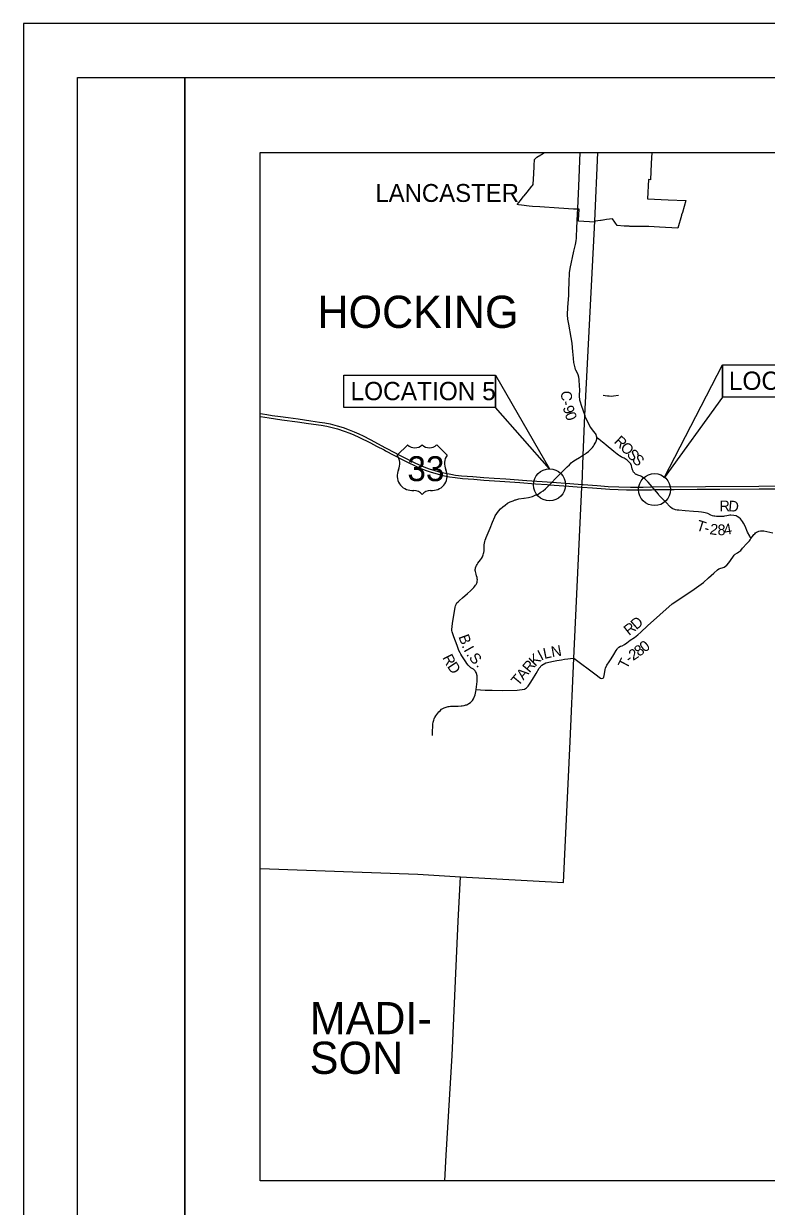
# Model space of a CAD drawing. Extents: x -51.9 to 34, y 0 to 23.3.
# Drawn here: x 0 to 6.91, y 11 to 22 of the extents above; entities that cross this region are included whole.
import ezdxf

# ---------------------------------------------------------------- set-up
doc = ezdxf.new("R2010")
doc.units = 0
for name, color, linetype in [('BR_P_Gen_Text', 7, 'Continuous'), ('Default', 7, 'Continuous'), ('GM_X_Corporation', 7, 'Continuous'), ('GM_X_Corporation_Text', 7, 'Continuous'), ('GM_X_County_Road', 7, 'Continuous'), ('GM_X_County_Road_Text', 7, 'Continuous'), ('GM_X_Minor_River', 7, 'Continuous'), ('GM_X_Township', 7, 'Continuous'), ('GM_X_Township_Road', 7, 'Continuous'), ('GM_X_Township_Road_Text', 7, 'Continuous'), ('GM_X_Township_Text', 7, 'Continuous'), ('GM_X_US_Route', 7, 'Continuous'), ('GM_X_US_Shield', 7, 'Continuous'), ('SH_Border', 7, 'Continuous'), ('SH_Cut_Line', 7, 'Continuous'), ('SH_Text', 7, 'Continuous')]:
    doc.layers.add(name, color=color, linetype=linetype)

msp = doc.modelspace()

# ---------------------------------------------------------------- linework, layer by layer
at = {"layer": 'BR_P_Gen_Text'}
for points in [[(6.501, 18.827), (6.501, 18.527), (5.958, 17.777)], [(6.501, 18.827), (7.909, 18.827), (7.909, 18.527), (6.501, 18.527)], [(2.98, 18.732), (4.389, 18.732), (4.389, 18.431), (2.98, 18.431)], [(4.389, 18.431), (4.389, 18.732), (4.893, 17.86)]]:
    msp.add_lwpolyline(points, close=True, dxfattribs=at)
at = {"layer": 'Default'}
for centre in [(4.893, 17.711), (5.87, 17.666)]:
    msp.add_circle(centre, 0.149, dxfattribs=at)
at = {"layer": 'GM_X_Corporation'}
msp.add_lwpolyline([(5.845, 20.801), (5.839, 20.7), (5.833, 20.548), (5.812, 20.549), (5.805, 20.371), (5.997, 20.362), (6.162, 20.354), (6.129, 20.243), (6.122, 20.221), (6.121, 20.216), (6.087, 20.098), (5.915, 20.108), (5.816, 20.112), (5.805, 20.113), (5.791, 20.113), (5.787, 20.114), (5.699, 20.114), (5.641, 20.114), (5.634, 20.115), (5.588, 20.118), (5.521, 20.124), (5.477, 20.184), (5.422, 20.177), (5.392, 20.173), (5.389, 20.173), (5.372, 20.17), (5.367, 20.17), (5.343, 20.167), (5.313, 20.163), (5.313, 20.157), (5.313, 20.153), (5.162, 20.163), (5.162, 20.173), (5.167, 20.274), (5.159, 20.274), (5.157, 20.274), (5.117, 20.276), (4.979, 20.283), (4.801, 20.297), (4.734, 20.3), (4.702, 20.304), (4.631, 20.312), (4.605, 20.315), (4.591, 20.317), (4.622, 20.354), (4.648, 20.388), (4.652, 20.395), (4.656, 20.4), (4.685, 20.434), (4.729, 20.487), (4.735, 20.496), (4.742, 20.504), (4.747, 20.605), (4.75, 20.672), (4.751, 20.682), (4.754, 20.737), (4.769, 20.752), (4.771, 20.754), (4.776, 20.758), (4.811, 20.78), (4.822, 20.787), (4.847, 20.801), (5.845, 20.801)], dxfattribs=at)
at = {"layer": 'GM_X_County_Road'}
for points in [[(5.156, 20.282), (5.165, 20.487), (5.177, 20.801)], [(5.143, 20.004), (5.145, 20.028), (5.148, 20.089), (5.151, 20.171), (5.156, 20.282)], [(5.334, 18.147), (5.333, 18.154), (5.331, 18.164), (5.326, 18.178), (5.319, 18.188), (5.302, 18.21), (5.276, 18.245), (5.269, 18.255), (5.236, 18.321), (5.228, 18.339), (5.223, 18.353), (5.189, 18.45), (5.18, 18.481), (5.176, 18.499), (5.173, 18.537), (5.174, 18.596), (5.173, 18.628), (5.169, 18.69), (5.166, 18.711), (5.16, 18.733), (5.149, 18.754), (5.138, 18.776), (5.135, 18.783), (5.13, 18.799), (5.12, 18.85), (5.112, 18.923), (5.11, 18.948), (5.102, 19.027), (5.094, 19.081), (5.071, 19.206), (5.063, 19.25), (5.059, 19.292), (5.063, 19.364), (5.071, 19.472), (5.073, 19.519), (5.075, 19.595), (5.079, 19.682), (5.084, 19.723), (5.119, 19.883), (5.133, 19.947), (5.139, 19.979), (5.143, 20.004)], [(5.058, 17.879), (5.078, 17.898), (5.094, 17.914), (5.11, 17.927), (5.133, 17.943), (5.172, 17.965), (5.19, 17.976), (5.206, 17.986), (5.226, 17.999), (5.235, 18.005), (5.256, 18.022), (5.272, 18.037), (5.284, 18.049), (5.291, 18.057), (5.301, 18.07), (5.309, 18.084), (5.317, 18.098), (5.322, 18.107), (5.326, 18.117), (5.33, 18.127), (5.332, 18.134), (5.334, 18.147)], [(4.302, 17.22), (4.339, 17.309), (4.362, 17.364), (4.384, 17.413), (4.388, 17.422), (4.401, 17.445), (4.418, 17.467), (4.437, 17.488), (4.458, 17.506), (4.479, 17.523), (4.503, 17.539), (4.515, 17.546), (4.528, 17.553), (4.553, 17.563), (4.572, 17.57), (4.579, 17.572), (4.606, 17.579), (4.653, 17.587), (4.656, 17.587), (4.697, 17.593), (4.733, 17.603), (4.76, 17.613), (4.786, 17.625), (4.812, 17.641), (4.834, 17.656), (4.856, 17.675), (4.893, 17.711), (4.905, 17.723), (4.916, 17.734), (4.946, 17.765), (4.971, 17.791), (5.027, 17.848), (5.058, 17.879)], [(3.803, 15.379), (3.805, 15.42), (3.807, 15.464), (3.808, 15.485), (3.81, 15.502), (3.813, 15.512), (3.816, 15.523), (3.819, 15.533), (3.824, 15.543), (3.827, 15.548), (3.836, 15.561), (3.864, 15.598), (3.875, 15.61), (3.888, 15.623), (3.894, 15.627), (3.9, 15.631), (3.907, 15.634), (3.913, 15.638), (3.921, 15.641), (3.931, 15.644), (3.94, 15.647), (3.949, 15.649), (3.958, 15.65), (3.971, 15.651), (3.995, 15.652), (4.044, 15.653), (4.071, 15.654), (4.081, 15.655), (4.1, 15.658), (4.107, 15.66), (4.113, 15.663), (4.123, 15.666), (4.133, 15.671), (4.142, 15.676), (4.158, 15.687), (4.167, 15.695), (4.171, 15.7), (4.175, 15.705), (4.185, 15.72), (4.2, 15.758), (4.204, 15.773), (4.208, 15.789), (4.211, 15.808), (4.218, 15.881), (4.22, 15.914), (4.218, 15.935), (4.213, 15.956), (4.209, 15.966), (4.204, 15.976), (4.2, 15.981), (4.196, 15.986), (4.184, 15.996), (4.162, 16.01), (4.152, 16.017), (4.146, 16.023), (4.136, 16.033), (4.124, 16.049), (4.115, 16.063), (4.076, 16.121), (4.068, 16.135), (4.06, 16.149), (4.05, 16.169), (4.032, 16.215), (4.002, 16.297), (3.989, 16.333), (3.986, 16.344), (3.984, 16.355), (3.983, 16.365), (3.989, 16.42), (4.015, 16.572), (4.018, 16.586), (4.02, 16.592), (4.023, 16.597), (4.025, 16.602), (4.031, 16.612), (4.042, 16.624), (4.054, 16.635), (4.083, 16.66), (4.129, 16.699), (4.158, 16.724), (4.173, 16.739), (4.189, 16.755), (4.199, 16.767), (4.205, 16.776), (4.21, 16.785), (4.215, 16.795), (4.218, 16.805), (4.22, 16.816), (4.221, 16.827), (4.22, 16.837), (4.219, 16.848), (4.214, 16.864), (4.209, 16.879), (4.206, 16.891), (4.204, 16.904), (4.202, 16.913), (4.202, 16.923), (4.203, 16.931), (4.204, 16.939), (4.209, 16.953), (4.213, 16.961), (4.218, 16.97), (4.227, 16.983), (4.25, 17.014), (4.26, 17.027), (4.268, 17.041), (4.273, 17.051), (4.276, 17.061), (4.279, 17.071), (4.282, 17.082), (4.284, 17.098), (4.286, 17.152), (4.288, 17.169), (4.291, 17.185), (4.293, 17.196), (4.299, 17.211), (4.302, 17.22)], [(4.211, 15.808), (4.25, 15.805), (4.294, 15.802), (4.359, 15.8), (4.454, 15.799), (4.591, 15.8)]]:
    msp.add_lwpolyline(points, dxfattribs=at)
at = {"layer": 'GM_X_Minor_River'}
msp.add_lwpolyline([(5.535, 18.541), (5.488, 18.535), (5.47, 18.533), (5.449, 18.534), (5.432, 18.536), (5.409, 18.539), (5.392, 18.542)], dxfattribs=at)
at = {"layer": 'GM_X_Township'}
for points in [[(2.202, 14.143), (3.666, 14.088), (4.065, 14.066), (5.024, 14.011), (5.084, 15.323), (5.12, 16.1), (5.194, 17.69), (5.195, 17.715), (5.206, 17.987), (5.222, 18.354), (5.315, 20.164), (5.343, 20.801)], [(3.918, 11.236), (3.931, 11.476), (3.986, 12.402), (4.043, 13.652), (4.065, 14.066)]]:
    msp.add_lwpolyline(points, dxfattribs=at)
at = {"layer": 'GM_X_Township_Road'}
for points in [[(5.788, 17.758), (5.787, 17.759), (5.779, 17.766), (5.77, 17.773), (5.761, 17.779), (5.747, 17.787), (5.737, 17.793), (5.724, 17.798), (5.713, 17.802), (5.703, 17.806), (5.699, 17.808), (5.694, 17.811), (5.69, 17.814), (5.685, 17.817), (5.682, 17.821), (5.678, 17.825), (5.675, 17.83), (5.672, 17.835), (5.67, 17.839), (5.667, 17.844), (5.665, 17.851), (5.662, 17.861), (5.659, 17.876), (5.656, 17.886), (5.654, 17.893), (5.65, 17.9), (5.648, 17.905), (5.642, 17.913), (5.634, 17.921), (5.626, 17.929), (5.614, 17.939), (5.605, 17.946), (5.596, 17.952), (5.586, 17.958), (5.577, 17.963), (5.57, 17.966), (5.559, 17.972), (5.545, 17.98), (5.533, 17.988), (5.521, 17.996), (5.491, 18.021), (5.42, 18.08), (5.398, 18.098), (5.384, 18.109), (5.371, 18.12), (5.348, 18.137), (5.334, 18.147)], [(5.91, 17.616), (5.905, 17.623), (5.87, 17.666), (5.858, 17.68), (5.848, 17.691), (5.809, 17.735), (5.788, 17.758)], [(6.766, 17.211), (6.755, 17.232), (6.736, 17.271), (6.712, 17.325), (6.697, 17.354), (6.689, 17.369), (6.669, 17.395), (6.655, 17.408), (6.639, 17.417), (6.629, 17.421), (6.608, 17.426), (6.581, 17.428), (6.57, 17.427), (6.559, 17.426), (6.543, 17.423), (6.522, 17.418), (6.511, 17.416), (6.49, 17.415), (6.469, 17.415), (6.447, 17.416), (6.431, 17.418), (6.42, 17.42), (6.41, 17.423), (6.394, 17.429), (6.364, 17.443), (6.342, 17.449), (6.326, 17.453), (6.306, 17.456), (6.279, 17.46), (6.231, 17.464), (6.156, 17.47), (6.096, 17.474), (6.079, 17.476), (6.065, 17.478), (6.057, 17.48), (6.04, 17.487), (6.033, 17.492), (6.019, 17.503), (5.972, 17.551), (5.924, 17.598), (5.911, 17.615), (5.91, 17.616)], [(6.766, 17.211), (6.78, 17.23), (6.795, 17.248), (6.802, 17.256), (6.81, 17.263), (6.819, 17.27), (6.828, 17.275), (6.839, 17.279), (6.855, 17.283), (6.866, 17.284), (6.877, 17.284), (6.887, 17.282), (6.969, 17.265)], [(5.113, 16.099), (5.12, 16.099), (5.327, 15.945), (5.356, 15.922), (5.368, 15.914), (5.378, 15.909), (5.388, 15.912), (5.396, 15.917), (5.398, 15.923), (5.402, 15.938), (5.408, 15.972), (5.411, 15.994), (5.413, 16.007), (5.426, 16.034), (5.446, 16.063), (5.467, 16.093), (5.49, 16.134), (5.512, 16.171), (5.523, 16.183), (5.526, 16.187), (5.537, 16.2), (5.554, 16.209), (5.569, 16.214), (5.589, 16.227), (5.613, 16.241), (5.643, 16.265), (5.683, 16.292), (5.713, 16.316), (5.743, 16.34), (5.805, 16.398), (6.034, 16.603), (6.216, 16.725), (6.324, 16.802), (6.371, 16.847), (6.396, 16.866), (6.42, 16.888), (6.455, 16.92), (6.469, 16.928), (6.516, 16.945), (6.53, 16.953), (6.542, 16.963), (6.56, 16.985), (6.597, 17.038), (6.611, 17.055), (6.62, 17.065), (6.641, 17.078), (6.654, 17.087), (6.671, 17.101), (6.689, 17.121), (6.729, 17.165), (6.753, 17.191), (6.759, 17.2), (6.766, 17.211)], [(4.591, 15.8), (4.659, 15.811), (4.677, 15.822), (4.693, 15.837), (4.712, 15.867), (4.734, 15.901), (4.768, 15.957), (4.796, 16.004), (4.821, 16.032), (4.858, 16.055), (4.875, 16.059), (4.913, 16.067), (4.961, 16.077), (5.004, 16.084), (5.031, 16.088), (5.064, 16.092), (5.113, 16.099)]]:
    msp.add_lwpolyline(points, dxfattribs=at)
at = {"layer": 'GM_X_US_Route'}
for points in [[(2.202, 18.375), (2.222, 18.371), (2.264, 18.364), (2.313, 18.357), (2.39, 18.346), (2.461, 18.337), (2.555, 18.323), (2.673, 18.306), (2.753, 18.295), (2.803, 18.286), (2.853, 18.277), (2.918, 18.26), (2.974, 18.243), (3.03, 18.223), (3.076, 18.205), (3.118, 18.186), (3.159, 18.166), (3.224, 18.131), (3.368, 18.056), (3.384, 18.047)], [(2.202, 18.346), (2.205, 18.346), (2.283, 18.333), (2.401, 18.316), (2.547, 18.296), (2.65, 18.282), (2.768, 18.265), (2.82, 18.255), (2.87, 18.244), (2.92, 18.23), (2.981, 18.211), (3.034, 18.191), (3.072, 18.176), (3.12, 18.155), (3.226, 18.101), (3.284, 18.071), (3.354, 18.035), (3.366, 18.028)], [(3.384, 18.047), (3.498, 17.988), (3.566, 17.952), (3.627, 17.921), (3.685, 17.895), (3.724, 17.879), (3.773, 17.861), (3.827, 17.843), (3.877, 17.829), (3.924, 17.818), (3.974, 17.809), (4.019, 17.802), (4.074, 17.795), (4.18, 17.787), (4.28, 17.78), (4.378, 17.773), (4.486, 17.765), (4.683, 17.751), (4.916, 17.734), (5.083, 17.722), (5.196, 17.714), (5.207, 17.713), (5.336, 17.704), (5.439, 17.696), (5.536, 17.692), (5.645, 17.689), (5.764, 17.689), (5.848, 17.691)], [(3.366, 18.028), (3.529, 17.944), (3.584, 17.915), (3.637, 17.889), (3.694, 17.864), (3.744, 17.845), (3.793, 17.828), (3.846, 17.813), (3.899, 17.799), (3.961, 17.786), (4.014, 17.778), (4.083, 17.77), (4.189, 17.762), (4.282, 17.755), (4.43, 17.745), (4.616, 17.731), (4.762, 17.721), (4.872, 17.713), (4.893, 17.711), (4.936, 17.708), (5.071, 17.698), (5.188, 17.69), (5.195, 17.689), (5.292, 17.682), (5.374, 17.676), (5.455, 17.671), (5.53, 17.667), (5.61, 17.664), (5.679, 17.664), (5.744, 17.665), (5.822, 17.665)], [(5.822, 17.665), (5.841, 17.665), (5.87, 17.666), (5.893, 17.666), (6.053, 17.667), (6.267, 17.669), (6.477, 17.671), (6.842, 17.673), (7.011, 17.675)], [(5.848, 17.691), (6.841, 17.699), (7.219, 17.702), (7.451, 17.704), (7.704, 17.705), (7.906, 17.707), (7.998, 17.707), (8.062, 17.705), (8.112, 17.7), (8.166, 17.694), (8.217, 17.685), (8.269, 17.674), (8.32, 17.661), (8.371, 17.646), (8.409, 17.634), (8.459, 17.615), (8.511, 17.593), (8.559, 17.57), (8.6, 17.549)]]:
    msp.add_lwpolyline(points, dxfattribs=at)
at = {"layer": 'GM_X_US_Shield'}
for p, q in [((3.573, 18.083), (3.476, 17.987)), ((3.939, 17.987), (3.843, 18.083)), ((3.611, 17.659), (3.63, 17.659)), ((3.785, 17.659), (3.804, 17.659))]:
    msp.add_line(p, q, dxfattribs=at)
for centre, radius, start, end in [((3.64, 18.152), 0.0966, 225.573, 314.427), ((3.775, 18.152), 0.0966, 225.573, 314.427), ((3.365, 17.909), 0.135, 334.5471, 35.0009), ((4.05, 17.909), 0.135, 144.9991, 205.4529), ((3.61, 17.794), 0.135, 154.8319, 270.6383), ((3.806, 17.794), 0.135, 269.3617, 25.1681), ((3.63, 17.562), 0.0966, 36.8699, 90), ((3.785, 17.562), 0.0966, 90, 143.1301)]:
    msp.add_arc(centre, radius, start, end, dxfattribs=at)
at = {"layer": 'SH_Border'}
for points in [[(0.5, 21.5), (1.5, 21.5), (1.5, 0.5), (0.5, 0.5)], [(1.5, 21.5), (33.5, 21.5), (33.5, 0.5), (1.5, 0.5)]]:
    msp.add_lwpolyline(points, close=True, dxfattribs=at)
at = {"layer": 'SH_Cut_Line'}
msp.add_lwpolyline([(0, 0), (34, 0), (34, 22), (0, 22)], close=True, dxfattribs=at)
at = {"layer": 'SH_Text'}
msp.add_lwpolyline([(2.202, 20.801), (12.658, 20.801), (12.658, 11.236), (2.202, 11.236)], close=True, dxfattribs=at)

# ---------------------------------------------------------------- texts
at = {"layer": 'BR_P_Gen_Text'}
for s, p in [('LOCATION 6', (6.561, 18.594)), ('LOCATION 5', (3.041, 18.498))]:
    msp.add_text(s, height=0.17, dxfattribs=at).set_placement(p)
at = {"layer": 'GM_X_Corporation_Text'}
msp.add_text('LANCASTER', height=0.1665, rotation=0, dxfattribs=at).set_placement((3.272, 20.342))
at = {"layer": 'GM_X_County_Road_Text'}
for s, rotation, p in [('C', 270.4684, (5.001, 18.585)), ('-', 280.2571, (5.003, 18.484)), ('9', 287.4394, (5.014, 18.431)), ('0', 289.2822, (5.033, 18.368)), ('B', 289.573, (4.044, 16.299)), ('.', 292.865, (4.074, 16.215)), ('I', 299.3828, (4.091, 16.176)), ('R', 297.1419, (3.893, 16.104)), ('D', 303.587, (3.937, 16.021)), ('.', 303.2685, (4.115, 16.134)), ('S', 308.5297, (4.138, 16.1)), ('.', 326.1761, (4.204, 16.025))]:
    msp.add_text(s, height=0.0999, rotation=rotation, dxfattribs=at).set_placement(p)
at = {"layer": 'GM_X_Township_Road_Text'}
for s, rotation, p in [('R', 316.525, (5.486, 18.106)), ('O', 313.8473, (5.544, 18.051)), ('S', 313.6408, (5.605, 17.987)), ('S', 313.6453, (5.652, 17.939)), ('R', 1.4853, (6.475, 17.463)), ('D', 355.3779, (6.554, 17.466)), ('T', 342.3931, (6.251, 17.291)), ('-', 343.5566, (6.324, 17.268)), ('2', 351.2533, (6.378, 17.253)), ('8', 0.4089, (6.456, 17.242)), ('4', 9.7309, (6.522, 17.243)), ('R', 38.2892, (5.632, 16.304)), ('D', 41.3625, (5.701, 16.358)), ('I', 28.1921, (4.815, 16.074)), ('L', 11.7823, (4.844, 16.091)), ('N', 10.3433, (4.917, 16.106)), ('2', 32.9807, (5.67, 16.072)), ('8', 36.1898, (5.726, 16.109)), ('0', 38.1854, (5.779, 16.148)), ('R', 49.9003, (4.707, 15.956)), ('K', 44.1435, (4.758, 16.017)), ('T', 63.2145, (5.613, 15.991)), ('-', 37.2711, (5.639, 16.048)), ('T', 50.0323, (4.602, 15.832)), ('A', 50.0333, (4.65, 15.889))]:
    msp.add_text(s, height=0.0999, rotation=rotation, dxfattribs=at).set_placement(p)
at = {"layer": 'GM_X_Township_Text'}
for s, p in [('HOCKING', (2.734, 19.17)), ('MADI-', (2.662, 12.601)), ('SON', (2.662, 12.232))]:
    msp.add_text(s, height=0.2996, rotation=0, dxfattribs=at).set_placement(p)
at = {"layer": 'GM_X_US_Shield'}
msp.add_text('33', height=0.2317, dxfattribs=at).set_placement((3.57, 17.745))

doc.saveas('drawing.dxf')
